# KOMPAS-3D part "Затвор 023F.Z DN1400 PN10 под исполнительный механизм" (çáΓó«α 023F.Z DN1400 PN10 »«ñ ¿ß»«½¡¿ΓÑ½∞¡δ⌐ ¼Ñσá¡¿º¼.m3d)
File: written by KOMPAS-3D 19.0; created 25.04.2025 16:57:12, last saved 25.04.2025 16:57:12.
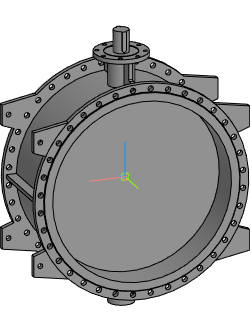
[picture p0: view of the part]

Document properties: Автор: Евгений; Полное имя файла: E:\Dendor Работа Сачек\3D для проекитирвщиков\1.7 Тип 023F.Z Затвор дисковый поворотный фланцевый с двумя эксцентриками\stp_Тип 023F.Z. Затвор под исполн. механизм\Затвор 023F.Z DN1400 PN10 под исполнительный механизм.m3d

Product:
- Part/product: Затвор 023F.Z DN1400 PN10 под исполнительный механизм

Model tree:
1. Операция без истории:1  (labels: Затвор 023F.Z DN1400 PN10 под исполнительный механизм)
